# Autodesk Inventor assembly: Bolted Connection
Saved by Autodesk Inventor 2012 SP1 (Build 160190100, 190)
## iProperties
Created: 2006-09
Part Number: Bolted Connection
Document SubType Name: Assembly
ClientObjectVersion: 1
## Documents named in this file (3)
- D:\Backup\CMU Work Temp\XX\Inv2012DynSim\Sub-Assemblies\Bolted Connection5.iam
- D:\Backup\CMU Work Temp\XX\Inv2012DynSim\Parts\M5-16.ipt
- D:\Backup\CMU Work Temp\XX\Inv2012DynSim\Parts\M5.ipt
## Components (2 placed, 2 different names)
1. Indented Hex Head Machine Screw - Metric M5 x 0.8 x 16:1
2. DIN 6923 M5:1
